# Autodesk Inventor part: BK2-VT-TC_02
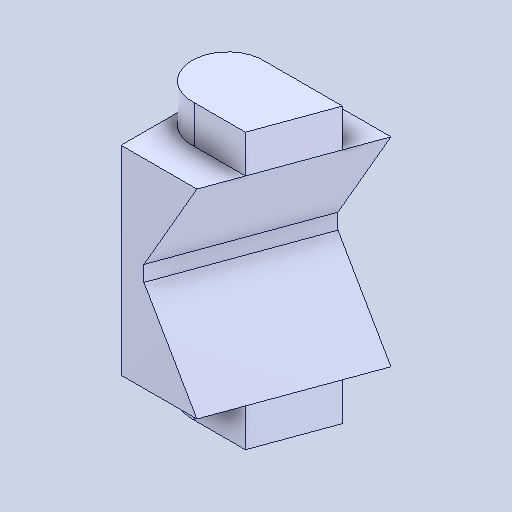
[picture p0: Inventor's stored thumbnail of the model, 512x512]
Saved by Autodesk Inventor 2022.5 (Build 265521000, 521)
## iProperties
Created: 2024-05
Part Number: BK2-VT-TC_02
Material: 一般
Document SubType Name: Modeling
Designer: ImaoCorp
Density: 1 g/cm^3
Appearance: 既定
Author: ImaoCorp
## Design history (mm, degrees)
feature "BK2-VT-TC_02"
node "ソリッド1"
